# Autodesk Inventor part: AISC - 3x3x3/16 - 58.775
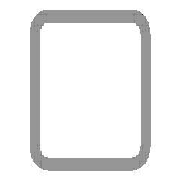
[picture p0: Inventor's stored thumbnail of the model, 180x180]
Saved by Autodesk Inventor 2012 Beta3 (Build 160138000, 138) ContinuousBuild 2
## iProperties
IsCustomPart: 1
Created: 2011-01
Part Number: AISC - 3x3x3/16 - 58.775
Material: Steel, Mild
Description: Tube
Document SubType Name: Modeling
Standard: ANSI
Designer: Beta-8540w
Standards Organization: ANSI
Language: en-US
Size Designation: 3x3x3/16
Categories: <MemberInstance><Categories><Category DisplayName="Structural Shapes" InternalName="089c4875-fa83-4c05-b084-43b9cc11f5ed" Mnemonic="GRDR"><CategoryParameter Dis
Stock Number: 3x3x3/16
Density: 7.86 g/cm^3
_CCFamilyMember: 9
_CCFamilyDisplayName: ANSI AISC (Square) - Tube
_FrameMemberDoc: Frame Member File
_Version: 15.0.0
_GetPNFromCC: 1
G_L: 58.775 in
G_W: 3.000 in
G_H: 3.000 in
+01816D91-1541-4907-A594-A35CBE7A7E0D+CUTDETAIL1: Cut
Author: Beta-8540w
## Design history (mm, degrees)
node "Start plane"
node "End plane"
sketch "Sketch"
  geometry: L1 (-38.1, -28.575)-(-38.1, 28.575); L2 (-28.575, 38.1)-(28.575, 38.1); L3 (38.1, 28.575)-(38.1, -28.575); L4 (28.575, -38.1)-(-28.575, -38.1); L5 (-28.575, 33.337)-(28.575, 33.338); L6 (33.338, 28.575)-(33.338, -28.575); L7 (28.575, -33.337)-(-28.575, -33.338); L8 (-33.338, -28.575)-(-33.338, 28.575); L9 (0, 56.102)-(0, -56.102) reference; L10 (-56.102, 0)-(56.102, 0) reference; A1 r 9.525 centre (-28.575, -28.575) between (-38.1, -28.575) and (-28.575, -38.1); A2 r 9.525 centre (-28.575, 28.575) between (-28.575, 38.1) and (-38.1, 28.575); A3 r 9.525 centre (28.575, 28.575) between (38.1, 28.575) and (28.575, 38.1); A4 r 9.525 centre (28.575, -28.575) between (28.575, -38.1) and (38.1, -28.575); A5 r 4.763 centre (-28.575, 28.575) between (-28.575, 33.337) and (-33.338, 28.575); A6 r 4.763 centre (28.575, 28.575) between (33.338, 28.575) and (28.575, 33.338); A7 r 4.763 centre (28.575, -28.575) between (28.575, -33.337) and (33.338, -28.575); A8 r 4.763 centre (-28.575, -28.575) between (-33.338, -28.575) and (-28.575, -33.338)
  constraints: 16 end point, 16 point on circle, 8 centre point, 8 tangent, 4 parallel, 3 equal radius, 2 perpendicular, 7 other
  dimensions: "d10" = 76.2 distance between parallel lines of L2 L4 (= G_H); "d11" = 76.2 distance between parallel lines of L1 L3 (= G_W); "d12" = 4.7625 distance between parallel lines of L3 L6 (= G_T); "d15" = 38.1 distance between parallel lines of L2 L10 (= 0.5 x d10); "d16" = 38.1 distance between parallel lines of L9 L3 (= 0.5 x d11); "d17" = 9.525 radius of A1 (= G_IR)
extrude "Body" new body sketch "Sketch" stored distance "d3" = 1492.89148 (= G_L); taper "d4" = 0 deg
node "Driven Length"
  sketch "Sketch3"
    geometry: L1 (0, 0)-(10, 0) reference
    constraints: 2 end point, 1 horizontal
  workplane "Work Plane3"
  sketch "Sketch4"
    geometry: L1 (-2, 0)-(12, 0) reference; L2 (-2, 1492.891)-(12, 1492.891) reference
    dimensions: "d19" = 1492.89148 distance between parallel lines of L1 L2 (derived)
workplane "Work Plane4"
split "Split1"
body "Solid1"
other parameters: "G_W" = 76.2 [user parameter; used in 1 equation term], "G_H" = 76.2 [user parameter; used in 1 equation term], "G_T" = 4.7625 [user parameter; used in 1 equation term], "G_IR" = 9.525 [user parameter; used in 1 equation term], "G_L" = 1492.89148 (= d19) [user parameter; used in 1 equation term], "G_OFFSET_START" = 0 [user parameter; used in 1 equation term], "G_OFFSET_END" = -31.10852 [user parameter; used in 1 equation term], "d13" = 0 (computed from G_OFFSET_START), "d14" = 1492.89148 (= G_OFFSET_END + B_L), "B_L" = 1524 [user parameter; used in 1 equation term], "d18" = 90 deg
